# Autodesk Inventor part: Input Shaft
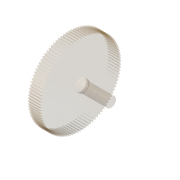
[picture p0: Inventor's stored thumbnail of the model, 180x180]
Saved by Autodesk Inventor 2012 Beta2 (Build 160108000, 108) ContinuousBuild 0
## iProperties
Created: 2011-01
Part Number: Input Shaft
Material: Steel
Document SubType Name: Modeling
Designer: Beta-8540w
Density: 1 g/cm^3
CustomPartVersion: 1
Author: Beta-8540w
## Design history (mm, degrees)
sketch "Main Sketch"
  geometry: L1 (0, 0)-(43, 0) reference; L2 (0, 0)-(0, 45); L3 (12, 45)-(12, 6); L4 (0, 45)-(12, 45); L5 (15, 6)-(15, 5); L6 (12, 6)-(15, 6); L7 (43, 5)-(43, 0); L8 (15, 5)-(43, 5)
  constraints: 16 end point, 5 horizontal, 4 vertical
  dimensions: "d3" = 90 diameter of L4 L1 (derived); "d4" = 12 diameter of L6 L1 (derived); "d5" = 10 diameter of L8 L1 (derived)
revolve "Revolution1" sketch "Main Sketch" stored, may be unused: angle "d6" = 0 deg
chamfer "Chamfer1" distance "d7" = 0.5; stored, may be unused: second distance "d8" = 0.125, angle "d9" = 45 deg
node "Retaining Ring Groove1"
node "Spur Gear Teeth2"
body "Solid1"
feature "iFeature27:1"
feature "Spur Gear Feature 2"
other parameters: "d0" = 0, "d1" = 0, "d2" = 0
